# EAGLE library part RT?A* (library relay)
Power PCB Relay SCHRACK bistable 1 pole 16 A, polarized bistable version Source: http://www.schrack.com/.. 5821.pdf
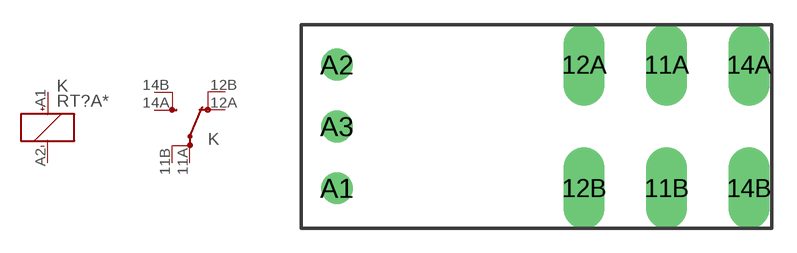
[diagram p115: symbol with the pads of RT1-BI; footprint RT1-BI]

Designator prefix K; gates 1=K+- 2=U-X2

## RT314A06 (MPN: RT314A06; OC_FARNELL: unknown; OC_NEWARK: 48M7945), RT314A12 (MF: TYCO ELECTRONICS; MPN: RT314A12; OC_FARNELL: unknown; OC_NEWARK: 08H3738), RT314A24 (MF: TYCO ELECTRONICS; MPN: RT314A24; OC_FARNELL: unknown; OC_NEWARK: 08H3739)  [RT1-BI]
11A  2:PA  pas
11B  2:PB  pas
12A  2:OA  pas
12B  2:OB  pas
14A  2:SA  pas
14B  2:SB  pas
A1  1:+  pas
A2  1:-  pas

## RTD14A05 (OC_FARNELL: unknown; OC_NEWARK: unknown), RTD14A06 (OC_FARNELL: unknown; OC_NEWARK: unknown), RTD14A12 (OC_FARNELL: unknown; OC_NEWARK: unknown), RTD14A24 (OC_FARNELL: unknown; OC_NEWARK: unknown)  [RT1-BI]
Pads as for RT1-BI

## Footprint RT1-BI (pad centres in mm)
Power PCB Relay , polarized bistable version SCHRACK 1 pole 16 A, pinning 5mm Source: http://www.schrack.com/.. 5821.pdf
drill 1.3 pad 2.5 long: 11A 7.56,3.78; 11B 7.56,-3.78; 12A 2.52,3.78; 12B 2.52,-3.78; 14A 12.6,3.78; 14B 12.6,-3.78
drill 1.3 round: A1 -12.6,-3.78; A2 -12.6,3.78; A3 -12.6,0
